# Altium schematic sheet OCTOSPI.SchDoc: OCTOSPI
size A4; Date: Not used; ApprovedBy: Not used; CheckedBy: Not used; Author: Not used; CompanyName: STMicroelectronics; DrawnBy: Not used; Engineer: Not used; Organization: Not used; Address1: Not used; Address2: Not used; Address3: Not used; Address4: Not used; DocumentNumber: 6; Revision: Not used; SheetNumber: 6; SheetTotal: 16
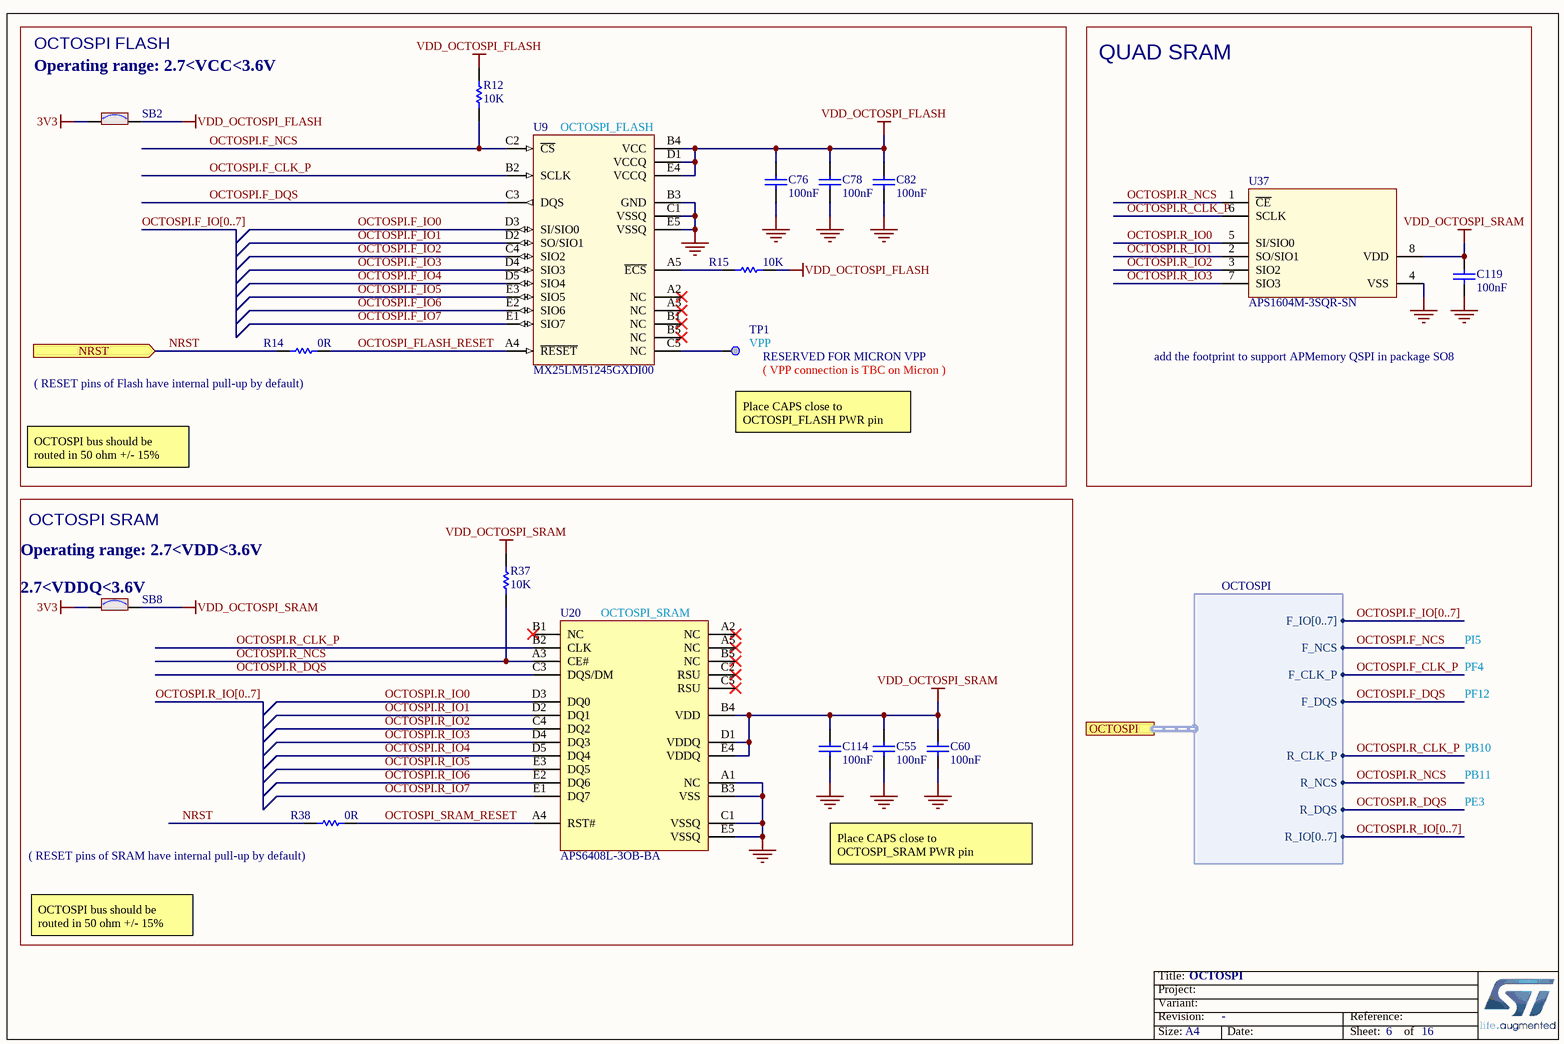
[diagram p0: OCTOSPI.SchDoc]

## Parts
C55  value 100nF  [C0402]
C60  value 100nF  [C0402]
C76  value 100nF  [C0402]
C78  value 100nF  [C0402]
C82  value 100nF  [C0402]
C114  value 100nF  [C0402]
C119  value 100nF  [C0402]  (hidden comment: Capacitor)
R12  value 10K  [R0603]
R14  value 0R  [R0603]
R15  value 10K  [R0603]
R37  value 10K  [R0603]
R38  value 0R  [R0603]
SB2  (no value)  [SOLDER-BRIDGE_R0603-0R]
SB8  (no value)  [SOLDER-BRIDGE_R0603-0R]
TP1  value VPP  [TP_SMD_1MM]  (no BOM)
U9  value MX25LM51245GXDI00  [ICC_BGA24_5X5-BALL-ARRAY_6X8_P1]
U20  value APS6408L-3OB-BA  [ICC_MINI-BGA24_6X8_P1]  (hidden comment: APS6408L-xOB)
U37  APS1604M-3SQR-SN  [ICC_SO8_5X4_P127]

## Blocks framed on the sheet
OCTOSPI FLASH: C76 C78 C82 R12 R14 R15 SB2 TP1 U9
QUAD SRAM: C119 U37
OCTOSPI SRAM: C55 C60 C114 R37 R38 SB8 U20

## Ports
NRST (in), OCTOSPI (harness OCTOSPI)

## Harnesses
OCTOSPI: F_DQS, F_CLK_P, F_NCS, R_CLK_P, R_NCS, R_DQS, R_IO[0..7], F_IO[0..7]

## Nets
3V3: SB2.1 SB8.1
GND: C55.1 C60.1 C76.1 C78.1 C82.1 C114.1 C119.1 U9.B3(GND) U9.C1(VSSQ) U9.E5(VSSQ) U20.A1(NC) U20.B3(VSS) U20.C1(VSSQ) U20.E5(VSSQ) U37.4(VSS)
VDD_OCTOSPI_FLASH: C76.2 C78.2 C82.2 R12.2 R15.1 SB2.2 U9.B4(VCC) U9.D1(VCCQ) U9.E4(VCCQ)
VDD_OCTOSPI_SRAM: C55.2 C60.2 C114.2 C119.2 R37.2 SB8.2 U20.B4(VDD) U20.D1(VDDQ) U20.E4(VDDQ) U37.8(VDD)
NRST: R14.1 R38.1 ; port NRST
OCTOSPI.F_CLK_P: U9.B2(SCLK) ; port OCTOSPI.F_CLK_P
OCTOSPI.F_DQS: U9.C3(DQS) ; port OCTOSPI.F_DQS
OCTOSPI.F_IO0: U9.D3(SI/SIO0)
OCTOSPI.F_IO1: U9.D2(SO/SIO1)
OCTOSPI.F_IO2: U9.C4(SIO2)
OCTOSPI.F_IO3: U9.D4(SIO3)
OCTOSPI.F_IO4: U9.D5(SIO4)
OCTOSPI.F_IO5: U9.E3(SIO5)
OCTOSPI.F_IO6: U9.E2(SIO6)
OCTOSPI.F_IO7: U9.E1(SIO7)
OCTOSPI.F_NCS: R12.1 U9.C2(~{CS}) ; port OCTOSPI.F_NCS
OCTOSPI.R_CLK_P: U20.B2(CLK) U37.6(SCLK) ; port OCTOSPI.R_CLK_P
OCTOSPI.R_DQS: U20.C3(DQS/DM) ; port OCTOSPI.R_DQS
OCTOSPI.R_IO0: U20.D3(DQ0) U37.5(SI/SIO0)
OCTOSPI.R_IO1: U20.D2(DQ1) U37.2(SO/SIO1)
OCTOSPI.R_IO2: U20.C4(DQ2) U37.3(SIO2)
OCTOSPI.R_IO3: U20.D4(DQ3) U37.7(SIO3)
OCTOSPI.R_IO4: U20.D5(DQ4)
OCTOSPI.R_IO5: U20.E3(DQ5)
OCTOSPI.R_IO6: U20.E2(DQ6)
OCTOSPI.R_IO7: U20.E1(DQ7)
OCTOSPI.R_NCS: R37.1 U20.A3(CE#) U37.1(~{CE}) ; port OCTOSPI.R_NCS
OCTOSPI_FLASH_RESET: R14.2 U9.A4(~{RESET})
OCTOSPI_SRAM_RESET: R38.2 U20.A4(RST#)
NetR15_2: R15.2 U9.A5(~{ECS})
NetTP1_1: TP1.1 U9.C5(NC)

Not connected (* = marked no-connect by the designer): U9 A2(NC)* A3(NC)* B1(NC)* B5(NC)*; U20 A2(NC)* A5(NC)* B1(NC)* B5(NC)* C2(RSU)* C5(RSU)*

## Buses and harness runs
bus OCTOSPI.F_IO[0..7]
bus OCTOSPI.R_IO[0..7]

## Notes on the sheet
- (near SB2) Operating range: 2.7<VCC<3.6V
  2.7<VCCQ<3.6V
- (near U9) OCTOSPI_FLASH
- (near R14) ( RESET pins of Flash have internal pull-up by default)
- (near TP1) ( VPP connection is TBC on Micron )
- (near TP1) RESERVED FOR MICRON VPP
- add the footprint to support APMemory QSPI in package SO8
- (near TP1) Place CAPS close to OCTOSPI_FLASH PWR pin
- OCTOSPI bus should be routed in 50 ohm +/- 15%
- (near SB8) Operating range: 2.7<VDD<3.6V
  2.7<VDDQ<3.6V
- (near U20) OCTOSPI_SRAM
- PI5
- PF12
- PF4
- PB10
- PB11
- (near R38) ( RESET pins of SRAM have internal pull-up by default)
- Place CAPS close to OCTOSPI_SRAM PWR pin
- PE3

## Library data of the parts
C55 C60 C76 C78 C82 C114 = MCD-00102: Capacitor, MLCC, 100nF, 16V, X7R, 10%, 0402, T=0,5mm; Manufacturer_Part_Number: CC0402KRX7R7BB104; Manufacturer: YAGEO; Alternate_Manufacturer_Part_Number: GCM155R71C104KA55D; Alternate_Manufacturer: MURATA; Provided_By: SUBCO
C119 = MCD-00006: Capacitor, MLCC, 100nF, 16V, X7R, 10%, 0402, T=0.5mm; Manufacturer_Part_Number: CC0402KRX7R7BB104; Manufacturer: YAGEO; Alternate_Manufacturer_Part_Number: GCM155R71C104KA55D; Alternate_Manufacturer: MURATA; Provided_By: SUBCO; ECCN_US: EAR99; ECCN_EU: NEC
R12 R15 R37 = MCD-00220: Resistor,10K,0603,1%,1/10W; Manufacturer_Part_Number: RC0603FR-0710KL; Manufacturer: YAGEO; Provided_By: Subcon; Initial_Board_Reference: MB1319
R14 R38 = MCD-00056: Resistor,0R,0603,5%,1/10W; Manufacturer_Part_Number: RC0603JR-070RL; Manufacturer: YAGEO; Provided_By: subcon; Initial_Board_Reference: MB1274
SB2 SB8 = MCD-00071: Solder Bridge ON; Part_Type: Mechanical; Provided_By: Subcon; Initial_Board_Reference: MB1274
TP1 = MCD-00074: Test Point 1mm; Part_Type: Mechanical; Initial_Board_Reference: MB1274
U9 = MCD-00246: Memory,Octo-SPI-NOR,512Mb,2048x16,133MHz,3V,DTR,BGA24, CMOS MXSMIO; Part_Type: IC; Manufacturer: MACRONIX; Provided_By: STM; Initial_Board_Reference: MB1331; ECCN_US: TBD; Remark: lead time = 16 weeks
U20 = MCD-01391: Memory, DDR Octal SPI PSRAM, 64Mb, 8Mx8, up to 133MHz@3V0, 104MHz@3V3, PASR; Part_Type: IC; Manufacturer: APMEMORY; BMS_Part_Number: 9171982; ECCN_US: 3A991B2B; Provided_By: SUBCO
U37 = MCD-01790: Quad-SPI PSRAM APS1604M-3SQR-SN with SOP-8L package; Part_Type: IC; Manufacturer: APMEMORY; Provided_By: SUBCO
